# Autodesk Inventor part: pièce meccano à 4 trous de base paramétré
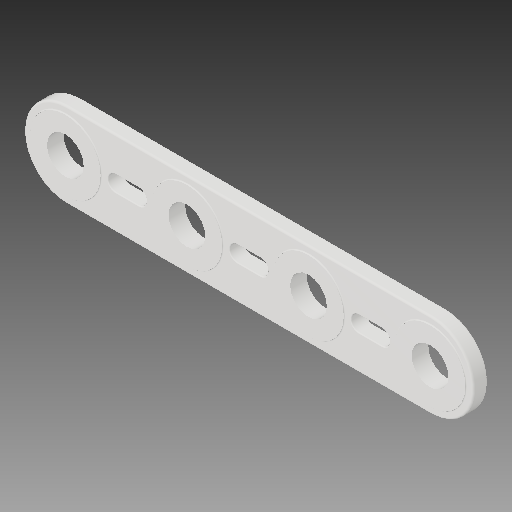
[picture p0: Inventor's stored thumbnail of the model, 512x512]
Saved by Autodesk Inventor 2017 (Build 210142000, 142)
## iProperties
Part Number: pièce meccano à 4 trous de base paramétré
Material: Plastique PC/ABS
Document SubType Name: Modeling
Designer: ficho
Density: 0.357273 g/cm^3
Appearance: Lisse - Blanc
Mass: 2.93367 g
Surface Area: 58.4524 cm^2
Volume: 8.2113 cm^3
Author: ficho
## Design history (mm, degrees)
sketch "Esquisse1"
  geometry: L1 (94.5, 11)-(0, 11); L2 (94.5, -11)-(0, -11); A1 r 11 centre (0, 0) between (0, 11) and (0, -11); A2 r 11 centre (94.5, 0) between (94.5, -11) and (94.5, 11); 1 further point
  constraints: 4 end point, 4 point on circle, 4 tangent, 2 centre point, 1 coincident
  dimensions: "d0" = 22 diameter of A1 (= largeur); "d1" = 22 diameter of A2 (= largeur); "d2" = 116.5 dimension on A2 A1 (= long)
extrude "Extrusion1" new body sketch "Esquisse1" distance "d3" = 3.8 (= ep); taper "d4" = 0 deg
fillet "Congé1" dims "d5" = 0.5
fillet "Congé2" dims "d6" = 0.5
sketch "Esquisse2"
  geometry: C1 r 9.15 at (0, 0); 1 further point
  constraints: 1 centre point, 1 coincident
  dimensions: "d14" = 18.3 diameter of C1
extrude "Extrusion2" join sketch "Esquisse2" distance "d15" = 0.25; taper "d16" = 0 deg
node "Plan de construction1"
mirror "Symétrie1"
fillet "Congé4" dims "d19" = 0.25
sketch "Esquisse4"
  geometry: 1 further point
hole "Perçage2" sketch "Esquisse4" at (0, 0) diameter "d20" = 9.5 (= alesage); stored, may be unused: countersink angle "d24" = 90 deg, drill point angle "d26" = 118 deg; dims "d21" = 6, "d22" = 4, "d23" = 2, "d25" = 8
pattern_linear "Réseau rectangulaire1" dims "d29" = 31.5 (= repet)
sketch "Esquisse5"
  geometry: L1 (18.75, 2)-(12.75, 2); L2 (18.75, -2)-(12.75, -2); C1 r 4.75 at (31.5, 0) reference; A1 r 2 centre (18.75, 0) between (18.75, -2) and (18.75, 2); A2 r 2 centre (12.75, 0) between (12.75, 2) and (12.75, -2); 1 further point
  constraints: 4 end point, 4 point on circle, 4 tangent, 2 centre point
  dimensions: "d30" = 4 diameter of A1; "d31" = 4 diameter of A2; "d32" = 6 distance of A2.centre A1.centre; "d33" = 12.75 distance of A2.centre point (0, 0)
extrude "Extrusion3" cut sketch "Esquisse5" stored distance "d35" = 0.25; taper "d36" = 0 deg
fillet "Congé5" dims "d37" = 0.25
pattern_linear "Réseau rectangulaire2" dims "d40" = 31.5 (= repet)
node "Solide1"
other parameters: "largeur" = 22 [user parameter; used in 2 equation terms], "long" = 116.5 [user parameter; used in 1 equation term], "ep" = 3.8 [user parameter; used in 2 equation terms], "alesage" = 9.5 [user parameter; used in 1 equation term], "d18" = -1.9 (= -0.5 x ep), "repet" = 31.5 [user parameter; used in 2 equation terms]
